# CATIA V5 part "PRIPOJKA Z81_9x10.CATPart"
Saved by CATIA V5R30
Part number: PRIPOJKA Z81/9x10
Bounding box of the stored display mesh (mm): x -17 to 7, y -6.2 to 6.2, z -5.5 to 5.5
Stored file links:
  C:\Users\ondra\Desktop\PŘÍLOHA P III\CATIA\PRIPOJKA Z81_9x10.CATPart
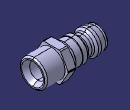
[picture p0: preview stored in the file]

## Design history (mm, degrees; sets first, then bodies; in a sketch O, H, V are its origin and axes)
Set1
  DatumSurface1 to DatumSurface62 "Z81/9x10"
  Join1: Elements (DatumSurface1; DatumSurface2; DatumSurface3; DatumSurface4; DatumSurface5; DatumSurface6; DatumSurface7; DatumSurface8; DatumSurface9; DatumSurface10; DatumSurface11; DatumSurface12; DatumSurface13; DatumSurface14; DatumSurface15; DatumSurface16; DatumSurface17; DatumSurface18; DatumSurface19; DatumSurface20; DatumSurface21; DatumSurface22; DatumSurface23; DatumSurface24; DatumSurface25; DatumSurface26; DatumSurface27; DatumSurface28; DatumSurface29; DatumSurface30; DatumSurface31; DatumSurface32; DatumSurface33; DatumSurface34; DatumSurface35; DatumSurface36; DatumSurface37; DatumSurface38; DatumSurface39; DatumSurface40; DatumSurface41; DatumSurface42; DatumSurface43; DatumSurface44; DatumSurface45; DatumSurface46; DatumSurface47; DatumSurface48; DatumSurface49; DatumSurface50; DatumSurface51; DatumSurface52; DatumSurface53; DatumSurface54; DatumSurface55; DatumSurface56; DatumSurface57; DatumSurface58; DatumSurface59; DatumSurface60; DatumSurface61; DatumSurface62)
Body1 (main body)
  CloseSurface1: CloseElement Join1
